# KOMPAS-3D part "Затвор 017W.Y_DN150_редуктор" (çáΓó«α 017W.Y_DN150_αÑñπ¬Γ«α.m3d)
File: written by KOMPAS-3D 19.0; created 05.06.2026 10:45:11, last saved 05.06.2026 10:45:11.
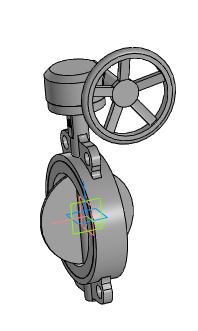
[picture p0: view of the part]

Document properties: Автор: Энергия; Полное имя файла: ..\..\..\3d для проектировщиков\x.x Тип 017W.Y(S) Затвор дисковый поворотный межфланцевый\Затвор 017W.Y(S)_DN50-DN1200_редуктор\Затвор 017W.Y_DN150_редуктор.a3d

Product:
- Part/product: Затвор 017W.Y_DN150_редуктор
    Масса: 14.3727

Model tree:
1. Операция без истории:1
